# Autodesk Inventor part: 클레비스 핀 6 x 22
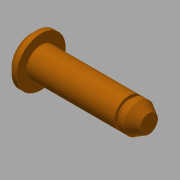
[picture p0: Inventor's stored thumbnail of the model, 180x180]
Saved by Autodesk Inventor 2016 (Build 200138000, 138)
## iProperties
IsCustomPart: 1
Created: 2017-08
Part Number: 클레비스 핀 6 x 22
Material: 강철
Description: 머리가 있는 클레비스 핀
Document SubType Name: Modeling
Standard: ISO 2341
Designer: mduedu
Standard Revision: Second edition 1986-11-01
Standards Organization: ISO
Language: ko-KR
Size Designation: B - 6 x 24
Categories: <MemberInstance><Categories><Category DisplayName="조임쇠" InternalName="e4da775c-781d-43d5-af7c-5136215cf5a6" Mnemonic="FSTN"><Category DisplayName="핀" InternalNa
Density: 7.85 g/cm^3
Appearance: 주황색
Author: mduedu
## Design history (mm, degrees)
sketch "스케치1"
  geometry: L1 (-2, 0)-(-2, 5); L2 (-2, 5)-(0, 5); L3 (0, 5)-(0, 3); L4 (0, 3)-(22, 3); L5 (22, 3)-(22, 0); L6 (-2, 0)-(22, 0); L7 (-7, 0)-(28, 0) reference; L8 (0, -1.96)-(0, 6.16) reference; C1 r 0.8 at (18.8, 0)
  constraints: 12 end point, 3 parallel, 2 collinear, 2 perpendicular, 1 centre point, 1 point on line, 1 vertical
  dimensions: "d0" = 6 diameter of L4 L6 (= NND); "d1" = 10 diameter of L2 L6 (= KOD); "d2" = 2 distance of L1.end L2.end (= KOH); "d3" = 22 distance of L3.end L4.end (= NLG); "d5" = 3.2 distance from line of L5 C1.centre (= DIST); "d6" = 1.6 diameter of C1 (= BOR)
revolve "본체" stored, may be unused: angle "d4" = 90 deg
workplane "Work Plane1"
node "작업 평면4"
sketch "스케치2"
  geometry: C1 r 3 at (0, 0) reference; C2 r 2.425 at (0, 0); 1 further point
  constraints: 1 centre point, 1 coincident
  dimensions: "d33" = 4.85 diameter of C2
extrude "돌출2" cut sketch "스케치2" distance "d34" = 0.7; taper "d35" = 0 deg
body "Solid1"
chamfer "모따기1" distance "d9" = 1 (= PHH2); stored, may be unused: angle "d10" = 45 deg (= FAWI2), second distance "d16" = 1 (= PHH2)
chamfer "모따기2" distance "d11" = 2 (= PHH1); stored, may be unused: angle "d12" = 30 deg (= FAWI1), second distance "d17" = 2 (= PHH1)
other parameters: "PHH1" = 2 [user parameter; used in 2 equation terms], "PHH2" = 1 [user parameter; used in 2 equation terms], "KOD" = 10 [user parameter; used in 1 equation term], "KOH" = 2 [user parameter; used in 1 equation term], "NND" = 6 [user parameter; used in 1 equation term], "FAWI1" = 30 deg [user parameter; used in 1 equation term], "FAWI2" = 45 deg [user parameter; used in 1 equation term], "DIST" = 3.2 [user parameter; used in 1 equation term], "BOR" = 1.6 [user parameter; used in 1 equation term], "NLG" = 22 [user parameter; used in 1 equation term], "d13" = 0, "d14" = 0, "d30" = 0, "d32" = 18
